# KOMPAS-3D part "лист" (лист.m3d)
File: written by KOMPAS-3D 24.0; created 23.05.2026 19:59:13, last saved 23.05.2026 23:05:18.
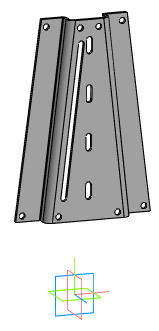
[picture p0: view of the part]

Document properties: Автор: R2D2; Полное имя файла: E:\Работа\Зайцев\GVKR1331M-1W-Fb-2P Задвижка шиберная с выдвижным штоком DN.ru Ду50-300 Ру16-10-6 с пневмоприводом\исходные материалы\DN100\лист.m3d

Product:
- Part/product: лист
    Масса: 1.297865
    Раздел спецификации: Прочие изделия
    Примечание: D040-08800

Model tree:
1. Эскиз:6  (with: Грань.Элемент выдавливания:15, Ребро.Элемент выдавливания:15)
2. Эскиз:7  (with: Грань.Элемент выдавливания:6, Ребро.Элемент выдавливания:6, Ребро.Элемент выдавливания:12)
3. Линейчатая обечайка:1
     Расстояние 1 = 10; Толщина листового тела = 4; Коэффициент = 0.5
4. Сгиб(1) - Линейчатая обечайка:1
     Радиус сгиба = 5; Коэффициент = 0.5; Величина сгиба = 5
5. Сгиб(2) - Линейчатая обечайка:1
     Радиус сгиба = 5; Коэффициент = 0.5; Величина сгиба = 5
6. Сгиб(3) - Линейчатая обечайка:1
     Радиус сгиба = 5; Коэффициент = 0.5; Величина сгиба = 5
7. Сгиб(4) - Линейчатая обечайка:1
     Радиус сгиба = 5; Коэффициент = 0.5; Величина сгиба = 5; Зазор = 1; Угол = 360; Параметр U, % = 100; Длина = 149
8. Эскиз:8  (with: Грань.Линейчатая обечайка:1, Ребро.Линейчатая обечайка:1)
9. Отверстие в листовом теле:1  (with: Грань.Линейчатая обечайка:1, Ребро.Линейчатая обечайка:1)
     Глубина выреза = 10; Диаметр отверстия = 8; Расстояние 1 = 7.5; Расстояние 2 = 7.5
10. Отверстие в листовом теле:2  (with: Грань.Линейчатая обечайка:1, Ребро.Линейчатая обечайка:1)
     Глубина выреза = 10; Диаметр отверстия = 8; Расстояние 1 = -7.5; Расстояние 2 = 7.5
11. Отверстие в листовом теле:3  (with: Грань.Линейчатая обечайка:1, Ребро.Линейчатая обечайка:1)
     Глубина выреза = 10; Диаметр отверстия = 8; Расстояние 1 = -84.1266; Расстояние 2 = 7.5
12. Отверстие в листовом теле:4  (with: Грань.Линейчатая обечайка:1, Ребро.Линейчатая обечайка:1)
     Глубина выреза = 10; Диаметр отверстия = 8; Расстояние 1 = -23.1878; Расстояние 2 = 7.5
13. Отверстие в листовом теле:5  (with: Грань.Линейчатая обечайка:1, Ребро.Линейчатая обечайка:1)
     Глубина выреза = 10; Диаметр отверстия = 8; Расстояние 1 = 7.5; Расстояние 2 = 244
14. Отверстие в листовом теле:6  (with: Грань.Линейчатая обечайка:1, Ребро.Линейчатая обечайка:1)
     Глубина выреза = 10; Диаметр отверстия = 8; Расстояние 1 = -7.5; Расстояние 2 = 244
15. Отверстие в листовом теле:7  (with: Грань.Линейчатая обечайка:1, Ребро.Линейчатая обечайка:1)
     Глубина выреза = 10; Диаметр отверстия = 8; Расстояние 1 = -31.4354; Расстояние 2 = 244
16. Отверстие в листовом теле:8  (with: Грань.Линейчатая обечайка:1, Ребро.Линейчатая обечайка:1)
     Глубина выреза = 10; Диаметр отверстия = 8; Расстояние 1 = -19.9235; Расстояние 2 = 244
17. Эскиз:9  (with: Грань.Линейчатая обечайка:1, Ребро.Линейчатая обечайка:1)
18. Эскиз:10  (with: Грань.Линейчатая обечайка:1, Ребро.Линейчатая обечайка:1)
19. Вырез в листовом теле:1
     Глубина выреза = 10
20. Вырез в листовом теле:2
     Глубина выреза = 10
21. Массив по сетке:1  (with: Вырез в листовом теле:2, Эскиз:9, Эскиз:10)  (4 pattern instances)
     Угол раствора = 90; Геометрический массив = 128

Expressions: 4*h; 2*h; v1424-70
Referenced files in E:\Работа\Зайцев\GVKR1331M-1W-Fb-2P Задвижка шиберная с выдвижным штоком DN.ru Ду50-300 Ру16-10-6 с пневмоприводом\исходные материалы\DN100\: GVKR1331M-1W-Fb-2P Задвижка шиберная с выдвижным штоком DN.ru Ду100 Ру16.a3d
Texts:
  Затвор дисковый DN.ru Ду Ру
